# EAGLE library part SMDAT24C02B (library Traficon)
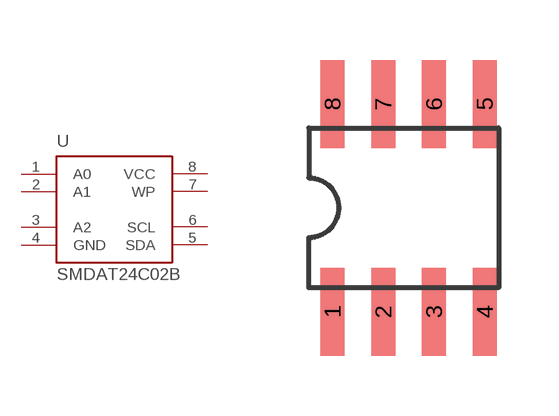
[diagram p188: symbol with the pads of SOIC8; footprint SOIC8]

Designator prefix U

## SMDAT24C02B  [SOIC8]
1  A0
2  A1
3  A2
4  GND
5  SDA
6  SCL
7  WP
8  VCC

## Footprint SOIC8 (pad centres in mm)
Small Outline IC
smd 0.6 x 2.2: 1 -1.905,-2.6; 2 -0.635,-2.6; 3 0.635,-2.6; 4 1.905,-2.6; 5 1.905,2.6; 6 0.635,2.6; 7 -0.635,2.6; 8 -1.905,2.6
